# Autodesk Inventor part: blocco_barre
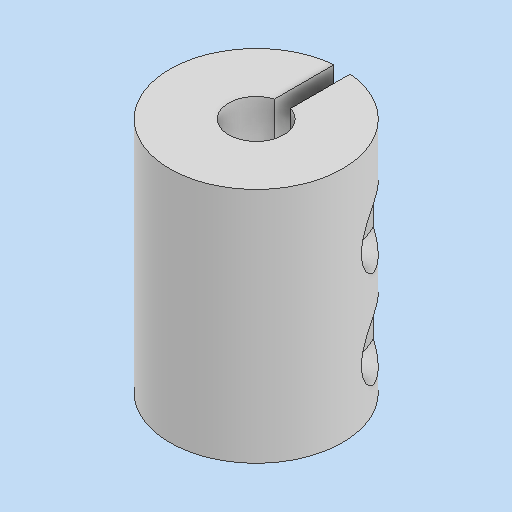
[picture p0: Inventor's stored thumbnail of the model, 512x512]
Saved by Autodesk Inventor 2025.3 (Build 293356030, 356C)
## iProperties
Created: 2025-12
Part Number: blocco_barre
Material: Generico
Document SubType Name: Modeling
Designer: Ryzen5700u
Density: 1 g/cm^3
Appearance: Default
Author: Ryzen5700u
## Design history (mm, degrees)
sketch "Schizzo1"
  geometry: C1 r 8 at (0, 0); 1 further point
  constraints: 1 centre point, 1 coincident
  dimensions: "d0" = 16 diameter of C1
extrude "Estrusione1" new body sketch "Schizzo1" distance "d1" = 22; taper "d2" = 0 deg
sketch "Schizzo2"
  geometry: C1 r 8 at (0, 0) reference; 2 further points
  constraints: 1 coincident
hole "Foro1" sketch "Schizzo2" at (0, 0) diameter "d3" = 5.1; stored, may be unused: countersink angle "d7" = 90 deg, drill point angle "d9" = 118 deg; dims "d4" = 6, "d5" = 10, "d6" = 5.7, "d8" = 11
sketch "Schizzo3"
  geometry: C1 r 8 at (0, 0) reference; 2 further points
  constraints: 1 coincident
hole "Foro2" sketch "Schizzo3" at (0, 0) diameter "d10" = 4; stored, may be unused: countersink angle "d14" = 90 deg, drill point angle "d16" = 118 deg; dims "d11" = 6, "d12" = 4, "d13" = 2, "d15" = 11
sketch "Schizzo4"
  geometry: L1 (0.75, 9.587)-(-0.75, 9.587); L2 (-0.75, 9.587)-(-0.75, -9.587); L3 (-0.75, -9.587)-(0.75, -9.587); L4 (0.75, -9.587)-(0.75, 9.587); L5 (0.75, 9.587)-(-0.75, -9.587); L6 (-0.75, 9.587)-(0.75, -9.587); C1 r 2 at (0, 0) reference; C2 r 8 at (0, 0) reference; 5 further points
  constraints: 12 end point, 2 midpoint, 2 parallel, 1 horizontal, 1 perpendicular
  dimensions: "d17" = 1.5 distance of L3.end L2.end
extrude "Estrusione2" cut sketch "Schizzo4" extent not by distance; stored distance "d18" = 0; taper "d19" = 0 deg
node "Piano di lavoro1"
node "Piano di lavoro2"
sketch "Schizzo5"
  geometry: L1 (6.111, 0)-(0, 0) reference; 3 further points
  dimensions: "d22" = 9 distance of point (2.931, 14) point (2.931, 5); "d23" = 5 distance from line of L1 point (2.931, 5)
hole "Foro3" sketch "Schizzo5" at (2.931, 5), (2.931, 14) diameter "d24" = 3.2; stored, may be unused: countersink angle "d28" = 90 deg, drill point angle "d30" = 118 deg; dims "d25" = 6, "d26" = 6.5, "d27" = 3.4, "d29" = 8
sketch "Schizzo6"
  geometry: C1 r 1.6 at (2.931, 5) reference; C2 r 1.6 at (2.931, 14) reference; C3 r 3 at (2.931, 5); C4 r 3 at (2.931, 14); 1 further point
  constraints: 2 centre point, 2 coincident
  dimensions: "d33" = 6 diameter of C3; "d34" = 6 diameter of C4
extrude "Estrusione3" cut sketch "Schizzo6" distance "d31" = 10; taper "d32" = 0 deg
mirror "Speculare1"
sketch "Schizzo7"
  geometry: C1 r 3 at (-2.931, 14); A1 r 1.6 centre (-2.931, 5) between (-1.928, 6.247) and (-1.928, 3.753) reference; A2 r 1.6 centre (-2.931, 14) between (-1.928, 15.247) and (-1.928, 12.753) reference; A3 r 3 centre (-2.931, 5) between (-1.928, 7.828) and (-1.928, 2.172) reference; 5 further points
  constraints: 2 coincident, 1 centre point, 2 other
extrude "Estrusione4" cut sketch "Schizzo7" distance "d35" = 1.4; taper "d36" = 0 deg
mirror "Speculare2"
chamfer "Smusso1" distance "d37" = 1; stored, may be unused: second distance "d38" = 2, angle "d39" = 45 deg
node "Solido1"
node "Linea chiusa proiettata1"
other parameters: "d20" = -4.5, "d21" = -5
